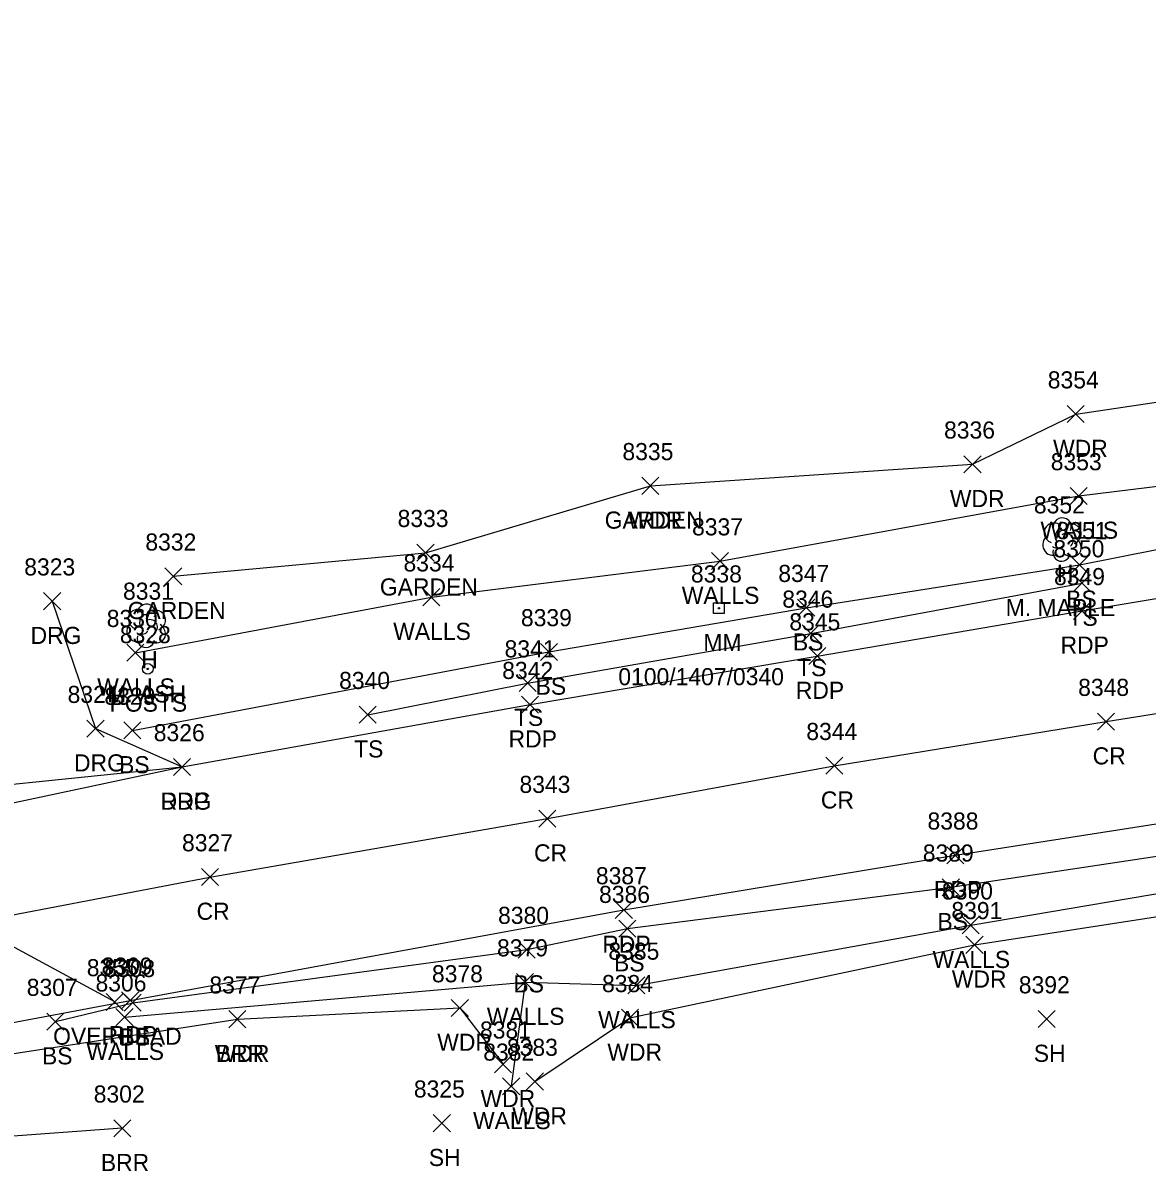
# Model space of a CAD drawing. Extents: x 1611797 to 1633212, y 298978 to 305475.
# Drawn here: x 1627265 to 1627396.2, y 304123.9 to 304258 of the extents above; entities that cross this region are included whole.
import ezdxf

# ---------------------------------------------------------------- set-up
doc = ezdxf.new("R2010")
doc.units = 0
for name, color, linetype in [('L_A', 7, 'Continuous'), ('L_C', 7, 'Continuous'), ('L_I', 7, 'Continuous'), ('L_TIC', 7, 'Continuous'), ('LABL', 7, 'Continuous'), ('LAPB', 7, 'Continuous'), ('LAWA', 7, 'Continuous'), ('LELB', 7, 'Continuous'), ('LPST', 7, 'Continuous'), ('LTD', 7, 'Continuous'), ('LWS', 7, 'Continuous'), ('P_A', 7, 'Continuous'), ('P_I', 7, 'Continuous'), ('P_TIC', 7, 'Continuous'), ('PET', 7, 'Continuous'), ('PRC', 7, 'Continuous'), ('R_A', 7, 'Continuous'), ('R_I', 7, 'Continuous'), ('R_TIC', 7, 'Continuous'), ('RDG', 7, 'Continuous'), ('RDP', 7, 'Continuous'), ('S_A', 7, 'Continuous'), ('S_C', 7, 'Continuous'), ('S_I', 7, 'Continuous'), ('SRM', 7, 'Continuous'), ('U_A', 7, 'Continuous'), ('U_I', 7, 'Continuous'), ('U_TIC', 7, 'Continuous'), ('UCO', 7, 'Continuous')]:
    doc.layers.add(name, color=color, linetype=linetype)

msp = doc.modelspace()

# ---------------------------------------------------------------- linework, layer by layer
at = {"layer": 'L_TIC'}
for points in [[(1627386.86, 304211.28), (1627388.86, 304213.28)], [(1627388.86, 304211.28), (1627386.86, 304213.28)], [(1627374.81, 304205.42), (1627376.81, 304207.42)], [(1627376.81, 304205.42), (1627374.81, 304207.42)], [(1627337.2, 304202.9), (1627339.2, 304204.9)], [(1627339.2, 304202.9), (1627337.2, 304204.9)], [(1627337.2, 304202.9), (1627339.2, 304204.9)], [(1627339.2, 304202.9), (1627337.2, 304204.9)], [(1627387.21, 304201.72), (1627389.21, 304203.72)], [(1627389.21, 304201.72), (1627387.21, 304203.72)], [(1627310.95, 304195.09), (1627312.95, 304197.09)], [(1627312.95, 304195.09), (1627310.95, 304197.09)], [(1627345.33, 304194.11), (1627347.33, 304196.11)], [(1627347.33, 304194.11), (1627345.33, 304196.11)], [(1627387.31, 304193.67), (1627389.31, 304195.67)], [(1627389.31, 304193.67), (1627387.31, 304195.67)], [(1627281.5, 304192.34), (1627283.5, 304194.34)], [(1627283.5, 304192.34), (1627281.5, 304194.34)], [(1627387.6, 304191.55), (1627389.6, 304193.55)], [(1627389.6, 304191.55), (1627387.6, 304193.55)], [(1627311.64, 304189.9), (1627313.64, 304191.9)], [(1627313.64, 304189.9), (1627311.64, 304191.9)], [(1627355.4, 304188.67), (1627357.4, 304190.67)], [(1627357.4, 304188.67), (1627355.4, 304190.67)], [(1627355.92, 304185.67), (1627357.92, 304187.67)], [(1627357.92, 304185.67), (1627355.92, 304187.67)], [(1627277.07, 304183.41), (1627279.07, 304185.41)], [(1627279.07, 304183.41), (1627277.07, 304185.41)], [(1627325.36, 304183.5), (1627327.36, 304185.5)], [(1627327.36, 304183.5), (1627325.36, 304185.5)], [(1627322.87, 304179.86), (1627324.87, 304181.86)], [(1627324.87, 304179.86), (1627322.87, 304181.86)], [(1627304.2, 304176.17), (1627306.2, 304178.17)], [(1627306.2, 304176.17), (1627304.2, 304178.17)], [(1627276.73, 304174.33), (1627278.73, 304176.33)], [(1627278.73, 304174.33), (1627276.73, 304176.33)], [(1627372.28, 304156.01), (1627374.28, 304158.01)], [(1627374.28, 304156.01), (1627372.28, 304158.01)], [(1627334.52, 304151.18), (1627336.52, 304153.18)], [(1627336.52, 304151.18), (1627334.52, 304153.18)], [(1627374.6, 304151.58), (1627376.6, 304153.58)], [(1627376.6, 304151.58), (1627374.6, 304153.58)], [(1627375.04, 304149.29), (1627377.04, 304151.29)], [(1627377.04, 304149.29), (1627375.04, 304151.29)], [(1627322.77, 304148.73), (1627324.77, 304150.73)], [(1627324.77, 304148.73), (1627322.77, 304150.73)], [(1627322.57, 304144.94), (1627324.57, 304146.94)], [(1627324.57, 304144.94), (1627322.57, 304146.94)], [(1627322.57, 304144.94), (1627324.57, 304146.94)], [(1627324.57, 304144.94), (1627322.57, 304146.94)], [(1627335.56, 304144.55), (1627337.56, 304146.55)], [(1627337.56, 304144.55), (1627335.56, 304146.55)], [(1627276.77, 304142.52), (1627278.77, 304144.52)], [(1627278.77, 304142.52), (1627276.77, 304144.52)], [(1627314.96, 304141.91), (1627316.96, 304143.91)], [(1627316.96, 304141.91), (1627314.96, 304143.91)], [(1627267.73, 304140.32), (1627269.73, 304142.32)], [(1627269.73, 304140.32), (1627267.73, 304142.32)], [(1627275.81, 304140.84), (1627277.81, 304142.84)], [(1627277.81, 304140.84), (1627275.81, 304142.84)], [(1627288.98, 304140.6), (1627290.98, 304142.6)], [(1627290.98, 304140.6), (1627288.98, 304142.6)], [(1627288.98, 304140.6), (1627290.98, 304142.6)], [(1627290.98, 304140.6), (1627288.98, 304142.6)], [(1627334.82, 304140.76), (1627336.82, 304142.76)], [(1627336.82, 304140.76), (1627334.82, 304142.76)], [(1627383.48, 304140.62), (1627385.48, 304142.62)], [(1627385.48, 304140.62), (1627383.48, 304142.62)], [(1627320, 304135.34), (1627322, 304137.34)], [(1627322, 304135.34), (1627320, 304137.34)], [(1627323.71, 304133.32), (1627325.71, 304135.32)], [(1627325.71, 304133.32), (1627323.71, 304135.32)], [(1627320.95, 304132.76), (1627322.95, 304134.76)], [(1627322.95, 304132.76), (1627320.95, 304134.76)], [(1627275.55, 304127.86), (1627277.55, 304129.86)], [(1627277.55, 304127.86), (1627275.55, 304129.86)], [(1627312.85, 304128.45), (1627314.85, 304130.45)], [(1627314.85, 304128.45), (1627312.85, 304130.45)]]:
    msp.add_lwpolyline(points, dxfattribs=at)
at = {"layer": 'LABL'}
msp.add_lwpolyline([(1627276.55, 304128.86), (1627261.68, 304127.78), (1627256.77, 304136.52), (1627289.98, 304141.6)], dxfattribs=at)
at = {"layer": 'LAPB'}
msp.add_lwpolyline([(1627282.5, 304193.34), (1627311.95, 304196.09), (1627338.2, 304203.9)], dxfattribs=at)
at = {"layer": 'LAWA'}
for points in [[(1627338.2, 304203.9), (1627375.81, 304206.42), (1627387.86, 304212.28), (1627425.51, 304217.87), (1627453.14, 304219.31), (1627462.7, 304223.21)], [(1627324.71, 304134.32), (1627335.82, 304141.76), (1627376.04, 304150.29), (1627431.44, 304158.84), (1627469.5, 304163.31)], [(1627289.98, 304141.6), (1627315.96, 304142.91), (1627321, 304136.34)]]:
    msp.add_lwpolyline(points, dxfattribs=at)
at = {"layer": 'LELB'}
for points in [[(1627277.73, 304175.33), (1627326.36, 304184.5), (1627356.4, 304189.67), (1627388.31, 304194.67), (1627425, 304201.95), (1627452.86, 304205.78), (1627473.83, 304210.7), (1627490.11, 304221.44), (1627547.4, 304229.46), (1627580.79, 304235.1), (1627592.66, 304237.63), (1627592.61, 304238.69), (1627588.92, 304240.06)], [(1627305.2, 304177.17), (1627323.87, 304180.86), (1627356.92, 304186.67), (1627388.6, 304192.55)], [(1627268.73, 304141.32), (1627277.77, 304143.52), (1627323.77, 304149.73), (1627335.52, 304152.18), (1627373.28, 304157.01), (1627433.07, 304166.03), (1627472.15, 304173.41)]]:
    msp.add_lwpolyline(points, dxfattribs=at)
at = {"layer": 'LPST'}
for radius in [0.625, 0.0833]:
    msp.add_circle((1627279.52, 304182.52), radius, dxfattribs=at)
at = {"layer": 'LTD'}
for p, q in [((1627386.24, 304197.68), (1627386.24, 304197.68)), ((1627386.24, 304197.68), (1627386.24, 304197.68)), ((1627279.32, 304187.6), (1627279.32, 304187.6)), ((1627279.32, 304187.6), (1627279.32, 304187.6))]:
    msp.add_line(p, q, dxfattribs=at)
for centre in [(1627386.29, 304199.11), (1627279.37, 304189.04)]:
    msp.add_arc(centre, 1.05, 335.5272, 180.9563, dxfattribs=at)
for centre, major_axis, ratio, start_param, end_param in [((1627385.45, 304198.35), (1.21, -0.51), 0.895232, 1.570796, 4.712389), ((1627387.28, 304198.26), (-1.14, -0.48), 0.949671, 1.570796, 4.712389), ((1627385.16, 304196.97), (0.58, -1.04), 0.959034, 3.141593, 6.283185), ((1627386.03, 304198.14), (-0.208, -0.792), 0.645439, 3.141593, 6.283185), ((1627386.74, 304197.51), (-0.5, 0.667), 0.989748, 3.141593, 6.283185), ((1627385.78, 304196.93), (-0.625, -0.083), 0.423636, 0, 3.141593), ((1627387.24, 304196.85), (-1.09, 0.79), 0.841452, 1.570796, 4.712389), ((1627386.24, 304196.18), (0.26, 1.06), 0.942809, 1.570796, 4.712389), ((1627278.53, 304188.27), (1.21, -0.51), 0.895232, 1.570796, 4.712389), ((1627279.12, 304188.06), (-0.208, -0.792), 0.645439, 3.141593, 6.283185), ((1627280.37, 304188.19), (-1.14, -0.48), 0.949671, 1.570796, 4.712389), ((1627278.24, 304186.89), (0.58, -1.04), 0.959034, 3.141593, 6.283185), ((1627279.82, 304187.44), (-0.5, 0.667), 0.989748, 3.141593, 6.283185), ((1627280.32, 304186.77), (-1.09, 0.79), 0.841452, 1.570796, 4.712389), ((1627279.32, 304186.1), (0.26, 1.06), 0.942809, 1.570796, 4.712389), ((1627278.87, 304186.85), (-0.625, -0.083), 0.423636, 0, 3.141593)]:
    msp.add_ellipse(centre, major_axis=major_axis, ratio=ratio, start_param=start_param, end_param=end_param, dxfattribs=at)
at = {"layer": 'LWS'}
for points in [[(1627278.07, 304184.41), (1627312.64, 304190.9), (1627346.33, 304195.11), (1627388.21, 304202.72), (1627423.15, 304207.03), (1627452.54, 304212.54), (1627466.91, 304217.37), (1627470.16, 304225.25)], [(1627276.81, 304141.84), (1627323.57, 304145.94), (1627336.56, 304145.55), (1627375.6, 304152.58), (1627433.74, 304162.44), (1627479.25, 304169.46)], [(1627323.57, 304145.94), (1627321.95, 304133.76)]]:
    msp.add_lwpolyline(points, dxfattribs=at)
at = {"layer": 'P_TIC'}
for points in [[(1627387.6, 304188.3), (1627389.6, 304190.3)], [(1627389.6, 304188.3), (1627387.6, 304190.3)], [(1627356.69, 304183.02), (1627358.69, 304185.02)], [(1627358.69, 304183.02), (1627356.69, 304185.02)], [(1627323.16, 304177.34), (1627325.16, 304179.34)], [(1627325.16, 304177.34), (1627323.16, 304179.34)], [(1627390.41, 304175.36), (1627392.41, 304177.36)], [(1627392.41, 304175.36), (1627390.41, 304177.36)], [(1627282.53, 304170.07), (1627284.53, 304172.07)], [(1627284.53, 304170.07), (1627282.53, 304172.07)], [(1627358.67, 304170.21), (1627360.67, 304172.21)], [(1627360.67, 304170.21), (1627358.67, 304172.21)], [(1627325.18, 304164.03), (1627327.18, 304166.03)], [(1627327.18, 304164.03), (1627325.18, 304166.03)], [(1627372.82, 304159.75), (1627374.82, 304161.75)], [(1627374.82, 304159.75), (1627372.82, 304161.75)], [(1627285.78, 304157.21), (1627287.78, 304159.21)], [(1627287.78, 304157.21), (1627285.78, 304159.21)], [(1627334.1, 304153.36), (1627336.1, 304155.36)], [(1627336.1, 304153.36), (1627334.1, 304155.36)], [(1627276.47, 304142.8), (1627278.47, 304144.8)], [(1627278.47, 304142.8), (1627276.47, 304144.8)]]:
    msp.add_lwpolyline(points, dxfattribs=at)
at = {"layer": 'PET'}
for points in [[(1627238.87, 304161.57), (1627283.53, 304171.07), (1627324.16, 304178.34), (1627357.69, 304184.02), (1627388.6, 304189.3), (1627425.09, 304195.36), (1627453.73, 304201), (1627467.59, 304203.62)], [(1627254.61, 304139.52), (1627277.47, 304143.8), (1627335.1, 304154.36), (1627373.82, 304160.75), (1627432.67, 304169.96), (1627478.46, 304176.47)]]:
    msp.add_lwpolyline(points, dxfattribs=at)
at = {"layer": 'PRC'}
msp.add_lwpolyline([(1627250.94, 304151.35), (1627286.78, 304158.21), (1627326.18, 304165.03), (1627359.67, 304171.21), (1627391.41, 304176.36), (1627426.14, 304181.92), (1627454.34, 304186.02), (1627471.65, 304189.25), (1627512.67, 304195.94), (1627550.92, 304201.88), (1627586.13, 304207.89), (1627632.19, 304215.08), (1627676.13, 304222.32), (1627729.71, 304231.42), (1627769.14, 304238.24), (1627805.83, 304244.92), (1627874.04, 304257.97)], dxfattribs=at)
at = {"layer": 'R_TIC'}
for points in [[(1627267.36, 304189.43), (1627269.36, 304191.43)], [(1627269.36, 304189.43), (1627267.36, 304191.43)], [(1627272.42, 304174.54), (1627274.42, 304176.54)], [(1627274.42, 304174.54), (1627272.42, 304176.54)], [(1627282.53, 304170.07), (1627284.53, 304172.07)], [(1627284.53, 304170.07), (1627282.53, 304172.07)], [(1627282.53, 304170.07), (1627284.53, 304172.07)], [(1627284.53, 304170.07), (1627282.53, 304172.07)]]:
    msp.add_lwpolyline(points, dxfattribs=at)
at = {"layer": 'RDG'}
msp.add_lwpolyline([(1627268.36, 304190.43), (1627273.42, 304175.54), (1627283.53, 304171.07)], dxfattribs=at)
at = {"layer": 'RDP'}
msp.add_lwpolyline([(1627238.87, 304161.57), (1627243.15, 304163.66), (1627247.04, 304167.34), (1627283.53, 304171.07)], dxfattribs=at)
at = {"layer": 'SRM'}
msp.add_lwpolyline([(1627345.58, 304190.23), (1627346.83, 304190.23), (1627346.83, 304188.98), (1627345.58, 304188.98)], close=True, dxfattribs=at)
msp.add_circle((1627346.2, 304189.61), 0.0833, dxfattribs=at)
at = {"layer": 'U_TIC'}
for points in [[(1627274.66, 304142.62), (1627276.66, 304144.62)], [(1627276.66, 304142.62), (1627274.66, 304144.62)]]:
    msp.add_lwpolyline(points, dxfattribs=at)
at = {"layer": 'UCO'}
msp.add_lwpolyline([(1627275.66, 304143.62), (1627240.91, 304162.42)], dxfattribs=at)

# ---------------------------------------------------------------- texts
at = {"layer": 'L_A'}
for s, p in [('WDR', (1627385.22, 304207.28)), ('WDR', (1627373.17, 304201.42)), ('GARDEN', (1627332.87, 304198.9)), ('WDR', (1627335.56, 304198.9)), ('WALLS', (1627383.75, 304197.72)), ('H', (1627385.67, 304192.68)), ('GARDEN', (1627306.62, 304191.09)), ('WALLS', (1627341.87, 304190.11)), ('BS', (1627386.75, 304189.67)), ('GARDEN', (1627277.17, 304188.34)), ('TS', (1627387.01, 304187.55)), ('WALLS', (1627308.18, 304185.9)), ('BS', (1627354.85, 304184.67)), ('H', (1627278.76, 304182.6)), ('TS', (1627355.33, 304181.67)), ('WALLS', (1627273.62, 304179.41)), ('BS', (1627324.8, 304179.5)), ('POSTS', (1627275.06, 304177.52)), ('TS', (1627322.28, 304175.86)), ('TS', (1627303.61, 304172.17)), ('BS', (1627276.17, 304170.33)), ('BS', (1627371.72, 304152.01)), ('BS', (1627333.96, 304147.18)), ('WALLS', (1627371.14, 304147.58)), ('WDR', (1627373.4, 304145.29)), ('BS', (1627322.21, 304144.73)), ('WALLS', (1627319.11, 304140.94)), ('WALLS', (1627319.11, 304140.94)), ('WALLS', (1627332.1, 304140.55)), ('BS', (1627276.22, 304138.52)), ('WDR', (1627313.32, 304137.91)), ('BS', (1627267.17, 304136.32)), ('WALLS', (1627272.35, 304136.84)), ('WDR', (1627287.34, 304136.6)), ('BRR', (1627287.46, 304136.6)), ('WDR', (1627333.18, 304136.76)), ('SH', (1627382.97, 304136.62)), ('WDR', (1627318.37, 304131.34)), ('WDR', (1627322.07, 304129.32)), ('WALLS', (1627317.5, 304128.76)), ('BRR', (1627274.04, 304123.86)), ('SH', (1627312.34, 304124.45))]:
    msp.add_text(s, height=2, dxfattribs=at).set_placement(p)
at = {"layer": 'L_C'}
for s, p in [('M. MAPLE', (1627379.69, 304188.68)), ('M. ASH', (1627274.79, 304178.6))]:
    msp.add_text(s, height=2, dxfattribs=at).set_placement(p)
at = {"layer": 'L_I'}
for s, p in [('8354', (1627384.6, 304215.28)), ('8336', (1627372.49, 304209.42)), ('8335', (1627334.94, 304206.9)), ('8335', (1627334.94, 304206.9)), ('8353', (1627384.95, 304205.72)), ('8352', (1627382.98, 304200.68)), ('8333', (1627308.69, 304199.09)), ('8337', (1627343.07, 304198.11)), ('8351', (1627385.62, 304197.67)), ('8332', (1627279.24, 304196.34)), ('8350', (1627385.26, 304195.55)), ('8334', (1627309.38, 304193.9)), ('8347', (1627353.14, 304192.67)), ('8331', (1627276.63, 304190.6)), ('8346', (1627353.61, 304189.67)), ('8330', (1627274.73, 304187.41)), ('8339', (1627323.09, 304187.5)), ('8328', (1627276.26, 304185.52)), ('8341', (1627321.18, 304183.86)), ('8340', (1627301.86, 304180.17)), ('8329', (1627274.46, 304178.33)), ('8389', (1627370.01, 304160.01)), ('8386', (1627332.21, 304155.18)), ('8390', (1627372.25, 304155.58)), ('8391', (1627373.35, 304153.29)), ('8380', (1627320.42, 304152.73)), ('8379', (1627320.3, 304148.94)), ('8379', (1627320.3, 304148.94)), ('8385', (1627333.3, 304148.55)), ('8308', (1627274.44, 304146.52)), ('8378', (1627312.7, 304145.91)), ('8307', (1627265.39, 304144.32)), ('8306', (1627273.42, 304144.84)), ('8377', (1627286.72, 304144.6)), ('8377', (1627286.72, 304144.6)), ('8384', (1627332.56, 304144.76)), ('8392', (1627381.22, 304144.62)), ('8381', (1627318.31, 304139.34)), ('8383', (1627321.45, 304137.32)), ('8382', (1627318.69, 304136.76)), ('8302', (1627273.21, 304131.86)), ('8325', (1627310.59, 304132.45))]:
    msp.add_text(s, height=2, dxfattribs=at).set_placement(p)
at = {"layer": 'P_A'}
for s, p in [('RDP', (1627386.09, 304184.3)), ('RDP', (1627355.18, 304179.02)), ('RDP', (1627321.65, 304173.34)), ('CR', (1627389.84, 304171.36)), ('RDP', (1627281.02, 304166.07)), ('CR', (1627358.11, 304166.21)), ('CR', (1627324.62, 304160.03)), ('RDP', (1627371.31, 304155.75)), ('CR', (1627285.22, 304153.21)), ('RDP', (1627332.59, 304149.36)), ('RDP', (1627274.96, 304138.8))]:
    msp.add_text(s, height=2, dxfattribs=at).set_placement(p)
at = {"layer": 'P_I'}
for s, p in [('8349', (1627385.33, 304192.3)), ('8345', (1627354.43, 304187.02)), ('8342', (1627320.9, 304181.34)), ('8348', (1627388.15, 304179.36)), ('8326', (1627280.22, 304174.07)), ('8344', (1627356.41, 304174.21)), ('8343', (1627322.92, 304168.03)), ('8388', (1627370.56, 304163.75)), ('8327', (1627283.52, 304161.21)), ('8387', (1627331.84, 304157.36)), ('8309', (1627274.13, 304146.8))]:
    msp.add_text(s, height=2, dxfattribs=at).set_placement(p)
at = {"layer": 'R_A'}
for s, p in [('DRG', (1627265.84, 304185.43)), ('DRG', (1627270.91, 304170.54)), ('DRG', (1627281.02, 304166.07)), ('DRP', (1627281.02, 304166.07))]:
    msp.add_text(s, height=2, dxfattribs=at).set_placement(p)
at = {"layer": 'R_I'}
for s, p in [('8323', (1627265.1, 304193.43)), ('8324', (1627270.16, 304178.54)), ('8326', (1627280.22, 304174.07)), ('8326', (1627280.22, 304174.07))]:
    msp.add_text(s, height=2, dxfattribs=at).set_placement(p)
at = {"layer": 'S_A'}
msp.add_text('MM', height=2, dxfattribs=at).set_placement((1627344.39, 304184.61))
at = {"layer": 'S_C'}
msp.add_text('0100/1407/0340', height=2, dxfattribs=at).set_placement((1627334.46, 304180.61))
at = {"layer": 'S_I'}
msp.add_text('8338', height=2, dxfattribs=at).set_placement((1627342.94, 304192.61))
at = {"layer": 'U_A'}
msp.add_text('OVERHEAD', height=2, dxfattribs=at).set_placement((1627268.47, 304138.62))
at = {"layer": 'U_I'}
msp.add_text('8355', height=2, dxfattribs=at).set_placement((1627272.4, 304146.62))

doc.saveas('drawing.dxf')
